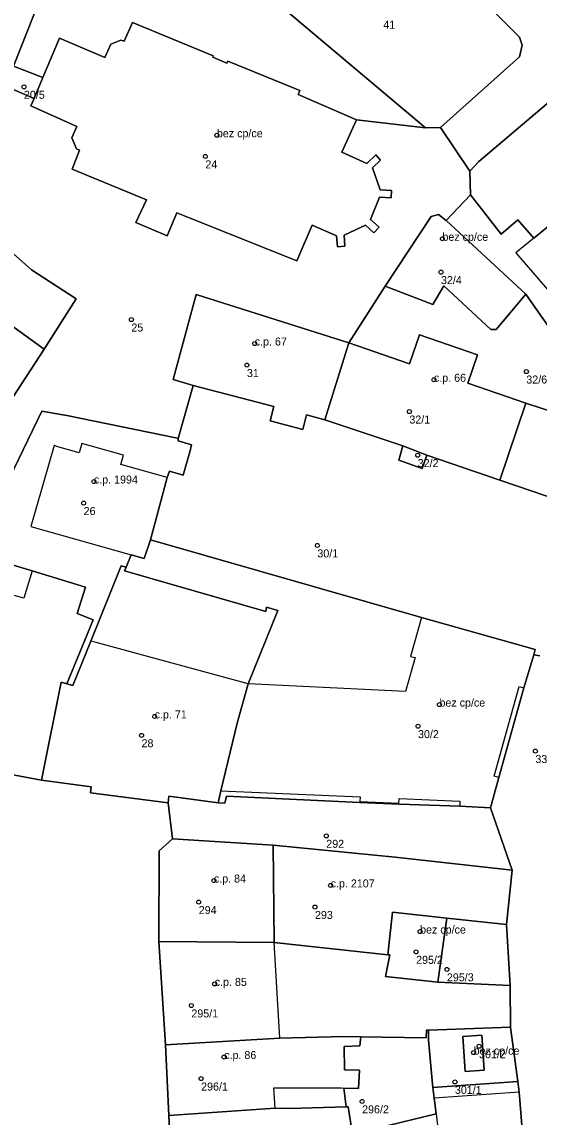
# Model space of a CAD drawing. Extents: x -878211 to -870363, y -1058464 to -1052522.
# Drawn here: x -874529.1 to -874464.5, y -1056123.6 to -1055986.7 of the extents above; entities that cross this region are included whole.
import ezdxf

# ---------------------------------------------------------------- set-up
doc = ezdxf.new("R2010")
doc.units = 0
for name, color, linetype in [('Vrstva 50', 7, 'Continuous'), ('Vrstva 51', 7, 'Continuous'), ('Vrstva 52', 7, 'Continuous')]:
    doc.layers.add(name, color=color, linetype=linetype)

msp = doc.modelspace()

# ---------------------------------------------------------------- linework, layer by layer
at = {"layer": 'Vrstva 50'}
for centre in [(-874528.88, -1055994.80994), (-874504.76, -1056000.85994), (-874506.2, -1056003.50994), (-874476.57, -1056013.79994), (-874476.75, -1056017.96994), (-874515.45, -1056023.89994), (-874500.03, -1056026.88994), (-874501.01, -1056029.58994), (-874466.08, -1056030.39994), (-874477.63, -1056031.41994), (-874480.7, -1056035.39994), (-874479.66, -1056040.84994), (-874520.14, -1056044.13994), (-874521.42, -1056046.83994), (-874492.2, -1056052.12994), (-874476.94, -1056072.01994), (-874512.54, -1056073.49994), (-874479.62, -1056074.71994), (-874514.18, -1056075.85994), (-874464.95, -1056077.82994), (-874491.09, -1056088.42994), (-874505.14, -1056094.00994), (-874490.54, -1056094.61994), (-874507.03, -1056096.70994), (-874492.5, -1056097.31994), (-874479.36, -1056100.38994), (-874479.86, -1056102.92994), (-874476.01, -1056105.11994), (-874505.03, -1056106.92994), (-874507.95, -1056109.62994), (-874472.67, -1056115.51994), (-874471.99, -1056114.72994), (-874503.85, -1056116.06994), (-874506.73, -1056118.76994), (-874475.01, -1056119.17994), (-874486.61, -1056121.61994)]:
    msp.add_circle(centre, 0.25, dxfattribs=at)
at = {"layer": 'Vrstva 51'}
for points in [[(-874531.94, -1055975.34), (-874536.45, -1055974.73), (-874542.67, -1055971.7), (-874545.31, -1055970.29), (-874545.8, -1055969.51), (-874548.01, -1055968.27), (-874558.51, -1055962.13), (-874564.97, -1055974.19), (-874554.22, -1055979.9), (-874554.05, -1055979.64), (-874548.35, -1055982.26), (-874535.23, -1055988.02), (-874536.92, -1055992.3), (-874531.18, -1055994.73), (-874530.19, -1055992.22), (-874526.75, -1055983.55), (-874532.84, -1055981.03), (-874531.31, -1055977.13), (-874525.33, -1055979.63), (-874525.45, -1055979.95), (-874519.76, -1055982.41), (-874518.32, -1055983.03), (-874517.63, -1055979.78)], [(-874486.49, -1055970.81), (-874487.58, -1055971.06), (-874500.28, -1055976.21), (-874501.67, -1055977.03), (-874502.28, -1055977.44), (-874503.54, -1055979.36), (-874501.27, -1055980.89), (-874478.67, -1055999.92), (-874476.79, -1055999.88), (-874466.93, -1055991.04), (-874466.6, -1055989.61), (-874466.92, -1055988.58), (-874484.77, -1055970.83)], [(-874527.62, -1055996.25), (-874528.01, -1055997.17), (-874522.28, -1055999.75), (-874522.88, -1056001.2), (-874522.31, -1056002.55), (-874521.94, -1056002.72), (-874522.87, -1056005.11), (-874513.57, -1056008.91), (-874514.9, -1056011.77), (-874510.99, -1056013.44), (-874509.78, -1056010.55), (-874494.78, -1056016.56), (-874492.86, -1056012.11), (-874489.79, -1056013.44), (-874489.67, -1056014.82), (-874488.76, -1056014.73), (-874488.85, -1056013.33), (-874486.18, -1056012.08), (-874485.13, -1056013.04), (-874484.48, -1056012.35), (-874485.54, -1056011.38), (-874484.42, -1056008.6), (-874482.98, -1056008.66), (-874482.95, -1056007.75), (-874484.37, -1056007.67), (-874485.33, -1056004.93), (-874484.29, -1056003.96), (-874484.9, -1056003.31), (-874486, -1056004.37), (-874489.15, -1056002.96), (-874487.31, -1055998.92), (-874494.62, -1055995.77), (-874494.41, -1055995.26), (-874503.4, -1055991.61), (-874503.51, -1055991.84), (-874505.27, -1055991.1), (-874505.24, -1055990.92), (-874515.32, -1055986.77), (-874516.34, -1055989.08), (-874516.75, -1055988.98), (-874518.02, -1055989.48), (-874518.76, -1055991.12), (-874524.44, -1055988.72), (-874526.52, -1055993.65)], [(-874472, -1056004.15), (-874473.15, -1056005.35), (-874473.05, -1056008.29), (-874469.21, -1056013.24), (-874467.16, -1056011.44), (-874465.14, -1056013.73), (-874462.61, -1056011.63), (-874459.52, -1056009.12), (-874458.63, -1056009.99), (-874457.43, -1056009.07), (-874456.52, -1056010.22), (-874455.75, -1056011.18), (-874452.02, -1056008.12), (-874439.18, -1055997.57), (-874447.03, -1055987.74), (-874453.47, -1055988.42)], [(-874526.52, -1055993.65), (-874530.19, -1055992.22), (-874531.18, -1055994.73), (-874527.62, -1055996.25)], [(-874535.12, -1056011.69), (-874542.68, -1056006.73), (-874544.39, -1056004.44), (-874549.89, -1056012.05), (-874542.96, -1056016.22), (-874542.79, -1056015.95), (-874537.35, -1056019.67), (-874526.35, -1056027.59), (-874522.37, -1056021.31), (-874527.95, -1056017.69), (-874533.65, -1056012.64)], [(-874453.92, -1056038.19), (-874449.79, -1056036.89), (-874451.64, -1056034.47), (-874452.02, -1056034.72), (-874453.2, -1056033.07), (-874452.91, -1056032.82), (-874454.79, -1056030.36), (-874455.28, -1056030.7), (-874456.79, -1056028.59), (-874456.41, -1056028.24), (-874455.26, -1056027.31), (-874451.76, -1056024.49), (-874455.83, -1056019.87), (-874462.61, -1056011.63), (-874465.14, -1056013.73), (-874467.16, -1056011.44), (-874469.21, -1056013.24), (-874473.05, -1056008.29), (-874476.11, -1056011.53), (-874466.13, -1056020.73)], [(-874466.13, -1056020.73), (-874476.11, -1056011.53), (-874477.05, -1056010.76), (-874477.96, -1056011), (-874483.73, -1056019.74), (-874477.75, -1056022.03), (-874476.38, -1056019.68), (-874470.51, -1056025.12), (-874469.86, -1056025.12)], [(-874542.79, -1056015.95), (-874542.96, -1056016.22), (-874549.89, -1056012.05), (-874553.75, -1056017.38), (-874550.74, -1056019.59), (-874547.06, -1056022.48), (-874530.32, -1056033.69), (-874526.35, -1056027.59), (-874537.35, -1056019.67)], [(-874483.73, -1056019.74), (-874488.27, -1056026.79), (-874480.68, -1056029.42), (-874479.43, -1056025.82), (-874472.2, -1056028.3), (-874473.39, -1056031.85), (-874466.16, -1056034.34), (-874457.22, -1056037.26), (-874454.72, -1056037.89), (-874454.39, -1056038.4), (-874453.92, -1056038.19), (-874466.13, -1056020.73), (-874469.86, -1056025.12), (-874470.51, -1056025.12), (-874476.38, -1056019.68), (-874477.75, -1056022.03)], [(-874491.28, -1056036.41), (-874488.27, -1056026.79), (-874507.36, -1056020.77), (-874510.22, -1056031.38), (-874507.72, -1056032.13), (-874497.63, -1056034.76), (-874498.09, -1056036.54), (-874494.03, -1056037.64), (-874493.56, -1056035.82)], [(-874466.16, -1056034.34), (-874473.39, -1056031.85), (-874472.2, -1056028.3), (-874479.43, -1056025.82), (-874480.68, -1056029.42), (-874488.27, -1056026.79), (-874491.28, -1056036.41), (-874481.5, -1056039.69), (-874478.5, -1056040.83), (-874469.4, -1056043.97)], [(-874457.22, -1056037.26), (-874466.16, -1056034.34), (-874469.4, -1056043.97), (-874465.34, -1056045.35), (-874460.6, -1056046.95), (-874459.04, -1056042.36)], [(-874481.5, -1056039.69), (-874482.02, -1056041.46), (-874479.12, -1056042.52), (-874478.5, -1056040.83)], [(-874526.7, -1056081.48), (-874524.23, -1056069.2), (-874523.5, -1056069.42), (-874521.27, -1056063.96), (-874520.23, -1056061.41), (-874522.24, -1056060.65), (-874521.2, -1056057.32), (-874527.85, -1056055.3), (-874534.56, -1056053.29), (-874534.24, -1056052.51), (-874534.86, -1056052.24), (-874536.92, -1056056.49), (-874539.04, -1056064.11), (-874539.7, -1056063.97), (-874543.16, -1056078.38)], [(-874503.58, -1056083.48), (-874486.92, -1056084.27), (-874481.92, -1056084.46), (-874474.4, -1056084.72), (-874470.56, -1056084.92), (-874469.53, -1056081.13), (-874466.41, -1056069.93), (-874465.16, -1056065.79), (-874464.97, -1056065.12), (-874479.19, -1056061.12), (-874513.05, -1056051.44), (-874513.85, -1056053.77), (-874515.49, -1056053.31), (-874516.11, -1056054.86), (-874516.29, -1056055.31), (-874498.64, -1056060.37), (-874498.56, -1056059.84), (-874497.16, -1056060.25), (-874500.84, -1056069.44), (-874502.22, -1056074.33), (-874504.26, -1056082.79), (-874504.62, -1056084.3), (-874503.78, -1056084.33)], [(-874504.26, -1056082.79), (-874502.22, -1056074.33), (-874500.84, -1056069.44), (-874497.16, -1056060.25), (-874498.56, -1056059.84), (-874498.64, -1056060.37), (-874516.29, -1056055.31), (-874516.11, -1056054.86), (-874516.73, -1056054.66), (-874520.53, -1056064.07), (-874522.75, -1056069.65), (-874523.5, -1056069.42), (-874524.23, -1056069.2), (-874526.7, -1056081.48), (-874520.47, -1056082.29), (-874520.56, -1056083.03), (-874510.84, -1056084.29), (-874510.75, -1056083.48), (-874504.62, -1056084.3)], [(-874510.31, -1056088.78), (-874497.72, -1056089.57), (-874482.48, -1056091.1), (-874467.86, -1056092.7), (-874470.56, -1056084.92), (-874474.4, -1056084.72), (-874481.92, -1056084.46), (-874486.92, -1056084.27), (-874503.58, -1056083.48), (-874503.78, -1056084.33), (-874504.62, -1056084.3), (-874510.75, -1056083.48), (-874510.84, -1056084.29)], [(-874512, -1056101.63), (-874497.62, -1056101.77), (-874497.72, -1056089.57), (-874510.31, -1056088.78), (-874511.99, -1056090.29)], [(-874483.4, -1056103.28), (-874482.79, -1056097.98), (-874476, -1056098.71), (-874468.58, -1056099.49), (-874467.86, -1056092.7), (-874482.48, -1056091.1), (-874497.72, -1056089.57), (-874497.62, -1056101.77)], [(-874477.13, -1056106.69), (-874476, -1056098.71), (-874482.79, -1056097.98), (-874483.4, -1056103.28), (-874483.15, -1056103.31), (-874483.69, -1056106.01)], [(-874468.1, -1056107.14), (-874468.58, -1056099.49), (-874476, -1056098.71), (-874477.13, -1056106.69)], [(-874468.1, -1056107.14), (-874477.13, -1056106.69), (-874483.69, -1056106.01), (-874483.15, -1056103.31), (-874483.4, -1056103.28), (-874497.62, -1056101.77), (-874512, -1056101.63), (-874511.17, -1056114.53), (-874496.91, -1056113.71), (-874488.88, -1056113.5), (-874486.78, -1056113.53), (-874478.61, -1056113.65), (-874478.58, -1056112.72), (-874478.31, -1056112.71), (-874468.04, -1056112.34)], [(-874477.81, -1056119.47), (-874478.32, -1056113.94), (-874478.31, -1056112.98), (-874478.31, -1056112.71), (-874478.58, -1056112.72), (-874478.61, -1056113.65), (-874486.78, -1056113.53), (-874486.81, -1056113.86), (-874486.88, -1056114.67), (-874488.84, -1056114.76), (-874488.82, -1056117.68), (-874486.95, -1056117.71), (-874487.04, -1056120), (-874488.91, -1056119.94), (-874488.6, -1056122.3), (-874488.36, -1056122.29), (-874487.79, -1056125.69), (-874477.34, -1056123.18), (-874477.6, -1056121.22), (-874477.76, -1056119.88)], [(-874477.81, -1056119.47), (-874477.76, -1056119.88), (-874467.15, -1056119.12), (-874468, -1056112.66), (-874468.04, -1056112.34), (-874478.31, -1056112.71), (-874478.31, -1056112.98), (-874478.32, -1056113.94)], [(-874510.78, -1056123.39), (-874497.49, -1056122.45), (-874495.65, -1056122.49), (-874488.6, -1056122.3), (-874488.91, -1056119.94), (-874487.04, -1056120), (-874486.95, -1056117.71), (-874488.82, -1056117.68), (-874488.84, -1056114.76), (-874486.88, -1056114.67), (-874486.81, -1056113.86), (-874486.78, -1056113.53), (-874488.88, -1056113.5), (-874496.91, -1056113.71), (-874511.17, -1056114.53)], [(-874471.35, -1056117.71), (-874473.72, -1056117.89), (-874474, -1056113.5), (-874471.65, -1056113.35)], [(-874471.35, -1056117.71), (-874471.65, -1056113.35), (-874474, -1056113.5), (-874473.72, -1056117.89)], [(-874466.98, -1056120.45), (-874467.15, -1056119.12), (-874477.76, -1056119.88), (-874477.6, -1056121.22), (-874477.34, -1056123.18), (-874487.79, -1056125.69), (-874487.48, -1056128.84), (-874486.47, -1056138.91), (-874475.82, -1056136.33), (-874467.6, -1056133.99), (-874466.08, -1056131.79)], [(-874497.49, -1056122.45), (-874510.78, -1056123.39), (-874510.41, -1056131.56), (-874493.94, -1056129.42), (-874492, -1056129.31), (-874487.48, -1056128.84), (-874487.79, -1056125.69), (-874488.36, -1056122.29), (-874488.6, -1056122.3), (-874495.65, -1056122.49)]]:
    msp.add_lwpolyline(points, close=True, dxfattribs=at)
for points in [[(-874484.77, -1055970.83), (-874466.92, -1055988.58), (-874466.6, -1055989.61), (-874466.93, -1055991.04), (-874476.79, -1055999.88), (-874473.15, -1056005.35), (-874472, -1056004.15), (-874453.47, -1055988.42), (-874447.03, -1055987.74), (-874451.64, -1055977.41)], [(-874526.75, -1055983.55), (-874530.19, -1055992.22), (-874526.52, -1055993.65), (-874524.44, -1055988.72), (-874518.76, -1055991.12), (-874518.02, -1055989.48), (-874516.75, -1055988.98), (-874516.34, -1055989.08), (-874515.32, -1055986.77), (-874505.24, -1055990.92), (-874505.27, -1055991.1), (-874503.51, -1055991.84), (-874503.4, -1055991.61), (-874494.41, -1055995.26), (-874494.62, -1055995.77), (-874487.31, -1055998.92), (-874478.67, -1055999.92), (-874501.27, -1055980.89)], [(-874534.86, -1056052.24), (-874526.63, -1056035.33), (-874524.01, -1056035.79), (-874523.53, -1056035.89), (-874509.9, -1056038.69), (-874509.59, -1056038.77), (-874507.72, -1056032.13), (-874510.22, -1056031.38), (-874507.36, -1056020.77), (-874488.27, -1056026.79), (-874483.73, -1056019.74), (-874477.96, -1056011), (-874477.05, -1056010.76), (-874476.11, -1056011.53), (-874473.05, -1056008.29), (-874473.15, -1056005.35), (-874476.79, -1055999.88), (-874478.67, -1055999.92), (-874487.31, -1055998.92), (-874489.15, -1056002.96), (-874486, -1056004.37), (-874484.9, -1056003.31), (-874484.29, -1056003.96), (-874485.33, -1056004.93), (-874484.37, -1056007.67), (-874482.95, -1056007.75), (-874482.98, -1056008.66), (-874484.42, -1056008.6), (-874485.54, -1056011.38), (-874484.48, -1056012.35), (-874485.13, -1056013.04), (-874486.18, -1056012.08), (-874488.85, -1056013.33), (-874488.76, -1056014.73), (-874489.67, -1056014.82), (-874489.79, -1056013.44), (-874492.86, -1056012.11), (-874494.78, -1056016.56), (-874509.78, -1056010.55), (-874510.99, -1056013.44), (-874514.9, -1056011.77), (-874513.57, -1056008.91), (-874522.87, -1056005.11), (-874521.94, -1056002.72), (-874522.31, -1056002.55), (-874522.88, -1056001.2), (-874522.28, -1055999.75), (-874528.01, -1055997.17), (-874527.62, -1055996.25), (-874531.18, -1055994.73)], [(-874533.65, -1056012.64), (-874527.95, -1056017.69), (-874522.37, -1056021.31), (-874526.35, -1056027.59), (-874530.32, -1056033.69)], [(-874460.6, -1056046.95), (-874465.34, -1056045.35), (-874469.4, -1056043.97), (-874478.5, -1056040.83), (-874479.12, -1056042.52), (-874482.02, -1056041.46), (-874481.5, -1056039.69), (-874491.28, -1056036.41), (-874493.56, -1056035.82), (-874494.03, -1056037.64), (-874498.09, -1056036.54), (-874497.63, -1056034.76), (-874507.72, -1056032.13), (-874509.59, -1056038.77), (-874509.62, -1056039.07), (-874507.92, -1056039.55), (-874508.08, -1056040.13), (-874508.97, -1056043.33), (-874510.67, -1056042.85), (-874510.99, -1056043.65), (-874513.05, -1056051.44), (-874479.19, -1056061.12), (-874464.97, -1056065.12), (-874465.16, -1056065.79), (-874464.39, -1056065.93)], [(-874534.56, -1056053.29), (-874527.85, -1056055.3), (-874521.2, -1056057.32), (-874522.24, -1056060.65), (-874520.23, -1056061.41), (-874521.27, -1056063.96), (-874523.5, -1056069.42), (-874522.75, -1056069.65), (-874520.53, -1056064.07), (-874516.73, -1056054.66), (-874516.11, -1056054.86), (-874515.49, -1056053.31), (-874513.85, -1056053.77), (-874513.05, -1056051.44), (-874510.99, -1056043.65), (-874510.67, -1056042.85), (-874508.97, -1056043.33), (-874508.08, -1056040.13), (-874507.92, -1056039.55), (-874509.62, -1056039.07), (-874509.59, -1056038.77), (-874509.9, -1056038.69), (-874523.53, -1056035.89), (-874524.01, -1056035.79), (-874526.63, -1056035.33), (-874534.86, -1056052.24)], [(-874464.39, -1056065.93), (-874465.16, -1056065.79), (-874466.41, -1056069.93), (-874469.53, -1056081.13), (-874470.56, -1056084.92), (-874467.86, -1056092.7), (-874468.58, -1056099.49), (-874468.1, -1056107.14), (-874468.04, -1056112.34), (-874468, -1056112.66), (-874467.15, -1056119.12), (-874466.98, -1056120.45), (-874466.08, -1056131.79)], [(-874510.41, -1056131.56), (-874510.78, -1056123.39), (-874511.17, -1056114.53), (-874512, -1056101.63), (-874511.99, -1056090.29), (-874510.31, -1056088.78), (-874510.84, -1056084.29), (-874520.56, -1056083.03), (-874520.47, -1056082.29), (-874526.7, -1056081.48), (-874543.16, -1056078.38)]]:
    msp.add_lwpolyline(points, dxfattribs=at)
at = {"layer": 'Vrstva 52'}
for points in [[(-874484.29, -1056003.96), (-874484.9, -1056003.31), (-874486, -1056004.37), (-874489.15, -1056002.96), (-874487.31, -1055998.92), (-874494.62, -1055995.77), (-874494.41, -1055995.26), (-874503.4, -1055991.61), (-874503.51, -1055991.84), (-874505.27, -1055991.1), (-874505.24, -1055990.92), (-874515.32, -1055986.77), (-874516.34, -1055989.08), (-874516.75, -1055988.98), (-874518.02, -1055989.48), (-874518.76, -1055991.12), (-874524.44, -1055988.72), (-874526.52, -1055993.65), (-874527.62, -1055996.25), (-874528.01, -1055997.17), (-874522.28, -1055999.75), (-874522.88, -1056001.2), (-874522.31, -1056002.55), (-874521.94, -1056002.72), (-874522.87, -1056005.11), (-874513.57, -1056008.91), (-874514.9, -1056011.77), (-874510.99, -1056013.44), (-874509.78, -1056010.55), (-874494.78, -1056016.56), (-874492.86, -1056012.11), (-874489.79, -1056013.44), (-874489.67, -1056014.82), (-874488.76, -1056014.73), (-874488.85, -1056013.33), (-874486.18, -1056012.08), (-874485.13, -1056013.04), (-874484.48, -1056012.35), (-874485.54, -1056011.38), (-874484.42, -1056008.6), (-874482.98, -1056008.66), (-874482.95, -1056007.75), (-874484.37, -1056007.67), (-874485.33, -1056004.93)], [(-874477.05, -1056010.76), (-874477.96, -1056011), (-874483.73, -1056019.74), (-874477.75, -1056022.03), (-874476.38, -1056019.68), (-874470.51, -1056025.12), (-874469.86, -1056025.12), (-874466.13, -1056020.73), (-874476.11, -1056011.53)], [(-874467.38, -1056015.54), (-874460.61, -1056023.43), (-874456.41, -1056028.24), (-874455.26, -1056027.31), (-874451.76, -1056024.49), (-874455.83, -1056019.87), (-874462.61, -1056011.63), (-874465.14, -1056013.73)], [(-874544.58, -1056018.73), (-874547.06, -1056022.48), (-874530.32, -1056033.69), (-874526.35, -1056027.59), (-874537.35, -1056019.67), (-874539.09, -1056022.32)], [(-874510.22, -1056031.38), (-874507.72, -1056032.13), (-874497.63, -1056034.76), (-874498.09, -1056036.54), (-874494.03, -1056037.64), (-874493.56, -1056035.82), (-874491.28, -1056036.41), (-874488.27, -1056026.79), (-874507.36, -1056020.77)], [(-874488.27, -1056026.79), (-874491.28, -1056036.41), (-874481.5, -1056039.69), (-874478.5, -1056040.83), (-874469.4, -1056043.97), (-874466.16, -1056034.34), (-874473.39, -1056031.85), (-874472.2, -1056028.3), (-874479.43, -1056025.82), (-874480.68, -1056029.42)], [(-874466.16, -1056034.34), (-874469.4, -1056043.97), (-874465.34, -1056045.35), (-874460.6, -1056046.95), (-874459.04, -1056042.36), (-874457.22, -1056037.26)], [(-874521.98, -1056040.53), (-874524.64, -1056039.78), (-874525.12, -1056039.64), (-874528.03, -1056049.77), (-874515.49, -1056053.31), (-874513.85, -1056053.77), (-874513.05, -1056051.44), (-874510.99, -1056043.65), (-874511.28, -1056043.56), (-874516.76, -1056042.01), (-874516.43, -1056040.86), (-874521.66, -1056039.39)], [(-874543.16, -1056078.38), (-874526.7, -1056081.48), (-874524.23, -1056069.2), (-874523.5, -1056069.42), (-874521.27, -1056063.96), (-874520.23, -1056061.41), (-874522.24, -1056060.65), (-874521.2, -1056057.32), (-874527.85, -1056055.3), (-874528.89, -1056058.73), (-874536.92, -1056056.49), (-874539.04, -1056064.11), (-874539.7, -1056063.97)], [(-874465.16, -1056065.79), (-874464.97, -1056065.12), (-874479.19, -1056061.12), (-874480.58, -1056066), (-874479.99, -1056066.15), (-874481.19, -1056070.37), (-874500.84, -1056069.44), (-874502.22, -1056074.33), (-874504.26, -1056082.79), (-874486.84, -1056083.54), (-874486.88, -1056084.12), (-874482.01, -1056084.34), (-874481.98, -1056083.75), (-874474.38, -1056084.09), (-874474.4, -1056084.72), (-874470.56, -1056084.92), (-874469.53, -1056081.13), (-874470.11, -1056080.98), (-874466.99, -1056069.77), (-874466.41, -1056069.93)], [(-874526.7, -1056081.48), (-874520.47, -1056082.29), (-874520.56, -1056083.03), (-874510.84, -1056084.29), (-874510.75, -1056083.48), (-874504.62, -1056084.3), (-874504.26, -1056082.79), (-874502.22, -1056074.33), (-874500.84, -1056069.44), (-874519.85, -1056064.26), (-874520.53, -1056064.07), (-874522.75, -1056069.65), (-874523.5, -1056069.42), (-874524.23, -1056069.2)], [(-874511.99, -1056090.29), (-874512, -1056101.63), (-874497.62, -1056101.77), (-874497.72, -1056089.57), (-874510.31, -1056088.78)], [(-874482.48, -1056091.1), (-874497.72, -1056089.57), (-874497.62, -1056101.77), (-874483.4, -1056103.28), (-874482.79, -1056097.98), (-874476, -1056098.71), (-874468.58, -1056099.49), (-874467.86, -1056092.7)], [(-874483.15, -1056103.31), (-874483.69, -1056106.01), (-874477.13, -1056106.69), (-874476, -1056098.71), (-874482.79, -1056097.98), (-874483.4, -1056103.28)], [(-874512, -1056101.63), (-874511.17, -1056114.53), (-874496.91, -1056113.71), (-874497.62, -1056101.77)], [(-874488.82, -1056117.68), (-874488.84, -1056114.76), (-874486.88, -1056114.67), (-874486.81, -1056113.86), (-874486.78, -1056113.53), (-874488.88, -1056113.5), (-874496.91, -1056113.71), (-874511.17, -1056114.53), (-874510.78, -1056123.39), (-874497.49, -1056122.45), (-874497.66, -1056119.91), (-874489.21, -1056119.93), (-874488.91, -1056119.94), (-874487.04, -1056120), (-874486.95, -1056117.71)], [(-874474, -1056113.5), (-874473.72, -1056117.89), (-874471.35, -1056117.71), (-874471.65, -1056113.35)], [(-874477.6, -1056121.22), (-874477.34, -1056123.18), (-874475.82, -1056136.33), (-874467.6, -1056133.99), (-874466.08, -1056131.79), (-874466.98, -1056120.45)], [(-874510.41, -1056131.56), (-874493.94, -1056129.42), (-874492, -1056129.31), (-874487.48, -1056128.84), (-874487.79, -1056125.69), (-874488.36, -1056122.29), (-874488.6, -1056122.3), (-874495.65, -1056122.49), (-874497.49, -1056122.45), (-874510.78, -1056123.39)]]:
    msp.add_lwpolyline(points, close=True, dxfattribs=at)

# ---------------------------------------------------------------- texts
at = {"layer": 'Vrstva 50'}
for s, p in [('41', (-874483.96, -1055987.549)), ('20/5', (-874528.88, -1055996.299)), ('bez cp/ce', (-874504.76, -1056001.11)), ('24', (-874506.2, -1056004.999)), ('bez cp/ce', (-874476.57, -1056014.05)), ('32/4', (-874476.75, -1056019.459)), ('25', (-874515.45, -1056025.389)), ('c.p. 67', (-874500.03, -1056027.139)), ('31', (-874501.01, -1056031.079)), ('c.p. 66', (-874477.63, -1056031.669)), ('32/6', (-874466.08, -1056031.889)), ('32/1', (-874480.7, -1056036.889)), ('32/2', (-874479.66, -1056042.339)), ('c.p. 1994', (-874520.14, -1056044.389)), ('26', (-874521.42, -1056048.329)), ('30/1', (-874492.2, -1056053.619)), ('bez cp/ce', (-874476.94, -1056072.27)), ('c.p. 71', (-874512.54, -1056073.75)), ('30/2', (-874479.62, -1056076.209)), ('28', (-874514.18, -1056077.349)), ('33/1', (-874464.95, -1056079.319)), ('292', (-874491.09, -1056089.919)), ('c.p. 84', (-874505.14, -1056094.26)), ('c.p. 2107', (-874490.54, -1056094.87)), ('294', (-874507.03, -1056098.199)), ('293', (-874492.5, -1056098.809)), ('bez cp/ce', (-874479.36, -1056100.639)), ('295/2', (-874479.86, -1056104.419)), ('295/3', (-874476.01, -1056106.609)), ('c.p. 85', (-874505.03, -1056107.179)), ('295/1', (-874507.95, -1056111.119)), ('c.p. 86', (-874503.85, -1056116.32)), ('bez cp/ce', (-874472.67, -1056115.77)), ('301/2', (-874471.99, -1056116.219)), ('296/1', (-874506.73, -1056120.259)), ('301/1', (-874475.01, -1056120.669)), ('296/2', (-874486.61, -1056123.109))]:
    msp.add_text(s, height=0.999996, dxfattribs=at).set_placement(p)

doc.saveas('drawing.dxf')
